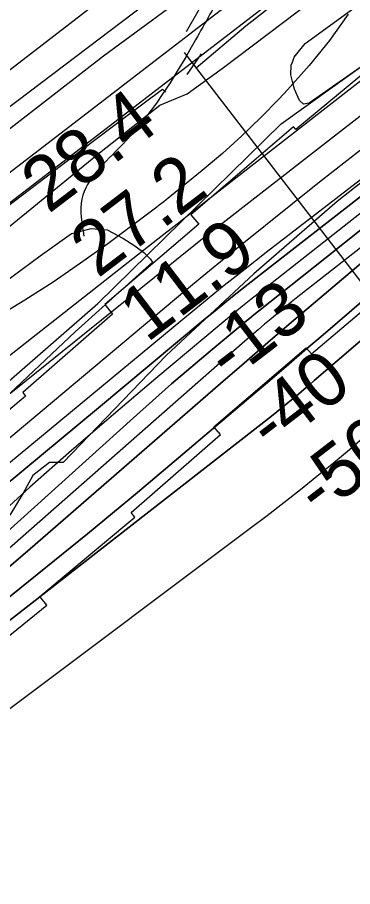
# Model space of a CAD drawing. Extents: x 3477039 to 3515015, y 546746 to 572297.
# Drawn here: x 3483912 to 3484325, y 559585 to 560657 of the extents above; entities that cross this region are included whole.
import ezdxf

# ---------------------------------------------------------------- set-up
doc = ezdxf.new("R2010")
doc.units = 0
for name, color, linetype in [('V-FLOD-BASE', 7, 'Continuous'), ('V-LEVE-TOET', 7, 'Continuous'), ('V-RIVR-EDGE', 7, 'Continuous'), ('V-RIVR-RANG', 7, 'Continuous'), ('V-ROAD-CNTR', 7, 'Continuous'), ('V-RRAP-FSHR', 7, 'Continuous'), ('V-RRAP-RVMT', 7, 'Continuous'), ('V-SITE-VEGE', 7, 'Continuous'), ('V-SURV-LINE', 7, 'Continuous'), ('V-TOPO-DPTH', 7, 'Continuous'), ('V-TOPO-MAJR', 7, 'Continuous'), ('V-TOPO-MINR', 7, 'Continuous'), ('V-TOPO-SHOR', 7, 'Continuous'), ('V-TOPO-WATR', 7, 'Continuous')]:
    doc.layers.add(name, color=color, linetype=linetype)

msp = doc.modelspace()

# ---------------------------------------------------------------- linework, layer by layer
at = {"layer": 'V-FLOD-BASE'}
for points in [[(3484132.1, 560594.4), (3484193.4, 560646.2), (3484285.1, 560718), (3484373.8, 560785.7), (3484477.9, 560867.4), (3484564.3, 560932.6)], [(3482382.9, 559248.9), (3482364.8, 559272), (3482401.5, 559301.2), (3482530.3, 559398.1), (3482669.5, 559501.2), (3482766.4, 559574.2), (3482900, 559673.3), (3483028.3, 559767.9), (3483135.8, 559846), (3483258.8, 559933.5), (3483358, 560002.3), (3483466.8, 560085.2), (3483528.9, 560136.6), (3483563.8, 560167.6), (3483599.3, 560196.2), (3483672.6, 560249.2), (3483768.9, 560321.6), (3483869.4, 560401), (3483974.7, 560480.9), (3484043.8, 560532.9), (3484090.5, 560567.9), (3484094.7, 560564.3)]]:
    msp.add_lwpolyline(points, dxfattribs=at)
at = {"layer": 'V-LEVE-TOET'}
for points in [[(3484546.9, 561015), (3484410.9, 560904), (3484276.1, 560799), (3484222.1, 560759.6), (3484143.1, 560701), (3484017.8, 560608.8), (3483855.8, 560483.3), (3483732.8, 560381.7), (3483580.9, 560267.9), (3483437.9, 560159.3), (3483302.5, 560057.2), (3483187.3, 559976.8), (3483022.3, 559850.1), (3482873.4, 559739.2), (3482703.1, 559613.2), (3482541.8, 559491.8), (3482433.6, 559410.7), (3482383.4, 559374.9), (3482356.2, 559355.3), (3482282.9, 559299.3), (3482194.2, 559234), (3482159.4, 559205)], [(3483226.6, 559872.4), (3483279.2, 559910.3), (3483320, 559941.2), (3483416.3, 560017.1), (3483486.7, 560072), (3483579, 560153.8), (3483683, 560231.4), (3483801.2, 560318.3), (3483902.9, 560399.5), (3484012.9, 560489.4), (3484087.4, 560548.4), (3484097.2, 560552.4), (3484121, 560562.3), (3484166, 560594.9), (3484275.3, 560677.2)]]:
    msp.add_lwpolyline(points, dxfattribs=at)
at = {"layer": 'V-RIVR-EDGE'}
msp.add_lwpolyline([(3484399.2, 560503), (3484305.9, 560429.7), (3484203.3, 560340.5), (3484095.2, 560239.6), (3483968.1, 560107.6), (3483951.5, 560107.6), (3483930.7, 560091.8), (3483919, 560069.7), (3483902.4, 560042.8)], dxfattribs=at)
at = {"layer": 'V-RIVR-RANG'}
msp.add_line((3484117.5, 560613.1), (3484483.4, 560137.6), dxfattribs=at)
at = {"layer": 'V-ROAD-CNTR'}
for points in [[(3487076.1, 563044), (3486779.2, 562810.3), (3486559.3, 562642), (3486392.2, 562506.5), (3486233.3, 562382.9), (3486038.4, 562229.6), (3485911.7, 562136), (3485621, 561911.1), (3485424, 561754.5), (3485308.3, 561665.3), (3485038, 561461.4), (3484792.2, 561271.1), (3484535.2, 561068.6), (3484336.9, 560919.3), (3484215.5, 560832), (3484122, 560761.2), (3483893.9, 560584.8), (3483720.5, 560448), (3483575.7, 560335.3), (3483437.8, 560223.9), (3483274.8, 560095.3), (3483188.4, 560027.1), (3483006, 559900.9)], [(3484219.5, 560834.8), (3484122, 560761.2), (3483893.9, 560584.8), (3483720.5, 560448), (3483575.7, 560335.3), (3483437.8, 560223.9), (3483274.8, 560095.3), (3483188.4, 560027.1), (3483006, 559900.9)], [(3484204, 560804.4), (3484205.9, 560791.9), (3484206, 560790.3), (3484205.7, 560787.7), (3484204.8, 560785.4), (3484195.1, 560767.8), (3484184.5, 560749.6), (3484168.1, 560722.7), (3484151.6, 560695.4), (3484134.1, 560663.6), (3484119.8, 560638.8)], [(3484138.2, 560611.7), (3484120.7, 560586.2)]]:
    msp.add_lwpolyline(points, dxfattribs=at)
msp.add_spline([(3484207, 560825.5), (3484220.2, 560798), (3484218.5, 560779.2), (3484197.4, 560742), (3484164.6, 560687.9), (3484129.2, 560625), (3484040.4, 560499), (3483991.3, 560432.4), (3483993.7, 560386.9)], degree=3, dxfattribs=at)
at = {"layer": 'V-RRAP-FSHR'}
msp.add_lwpolyline([(3481235.5, 558175), (3481260.4, 558193.2), (3481664.8, 558468.2), (3481750.1, 558561.3), (3481840.8, 558681.4), (3481906.4, 558774.6), (3482006.9, 558887.3), (3482130.2, 558983.5), (3482201, 559023.4), (3482476.9, 559192.1), (3482732, 559365.8), (3482809.3, 559398.5), (3482880.6, 559442.7), (3483189.7, 559671.5), (3483435.4, 559838.7), (3483794.7, 560115.6), (3484011.1, 560303.9), (3484237, 560525.2), (3484364.2, 560616.5), (3484735.6, 560876.4)], dxfattribs=at)
at = {"layer": 'V-RRAP-RVMT'}
for points in [[(3484495.5, 560702.4), (3484380.4, 560606.2), (3484372.1, 560615.4), (3484255.2, 560518.1), (3484252.3, 560521.4), (3484125.6, 560412.9), (3484135.6, 560401.4), (3484019.4, 560302.5), (3484029.1, 560290.7), (3483918.3, 560194), (3483921.9, 560189.6), (3483811.6, 560096.8), (3483801.4, 560108.9), (3483687.5, 560012.6), (3483683.1, 560017.4), (3483574.6, 559926.1), (3483571.2, 559930), (3483452, 559827.6)], [(3483452, 559827.6), (3483614.7, 559633.7), (3483734.2, 559733.9), (3483733, 559735.4), (3483842.4, 559825.2), (3483832.3, 559838.2), (3483948, 559931.9), (3483939.2, 559942.5), (3484056.5, 560040.4), (3484051.9, 560046), (3484162.2, 560142.1), (3484154, 560151.8), (3484267.9, 560248.9), (3484274.2, 560241.7), (3484399.6, 560347.6), (3484397.4, 560350.1), (3484617.7, 560539.2)]]:
    msp.add_lwpolyline(points, dxfattribs=at)
at = {"layer": 'V-SITE-VEGE'}
for points in [[(3484465.8, 560687.9), (3484350.6, 560606.2), (3484271.4, 560550.8), (3484264.3, 560549.7), (3484259.6, 560553.9), (3484253.3, 560568), (3484250.8, 560577.5), (3484248.7, 560585.7), (3484249.3, 560597.5), (3484250.8, 560601.5), (3484252.9, 560607.4), (3484266.5, 560624.4), (3484396, 560718.9)], [(3483806.4, 560264), (3483940, 560362.6), (3483978.4, 560390), (3484002.6, 560396.3), (3484022.6, 560394.4), (3484041.9, 560384.3), (3484056.6, 560374.8), (3484067.7, 560366.5), (3484075.3, 560358.8), (3484078.2, 560354.6), (3483982.9, 560268.7), (3483887.7, 560179.3)]]:
    msp.add_lwpolyline(points, dxfattribs=at)
at = {"layer": 'V-SURV-LINE'}
for points in [[(3483525, 560175.6), (3487277.1, 563062.8)], [(3487295.4, 563039), (3483543.3, 560151.8)]]:
    msp.add_lwpolyline(points, dxfattribs=at)
at = {"layer": 'V-TOPO-DPTH'}
for points in [[(3484837.9, 560882.1), (3484351.8, 560505.8), (3484318, 560479.6), (3484284.4, 560453.2), (3484250.9, 560426.7), (3484217.5, 560400), (3484184.2, 560373.2), (3484151.1, 560346.2), (3484118.2, 560319), (3483523.4, 559820.4), (3483490.6, 559793.6), (3483438.3, 559751.1), (3483431.5, 559745.7), (3483424.7, 559740.3), (3483417.7, 559735.2), (3483410.7, 559730.1), (3483341.6, 559681.1), (3483299.9, 559651.7), (3483258.1, 559622.4), (3483216.1, 559593.4)], [(3483157, 559406.5), (3483242.5, 559466.9), (3483327.8, 559527.6), (3483470.5, 559629.8), (3483484.2, 559639.7), (3483497.8, 559649.8), (3483511.3, 559660.1), (3483524.6, 559670.6), (3483643, 559764.7), (3483715, 559822.8), (3483786.6, 559881.5), (3483857.4, 559941.1), (3483927.6, 560001.4), (3484162, 560205.1), (3484191.2, 560230.3), (3484220.4, 560255.5), (3484249.7, 560280.6), (3484279.1, 560305.6), (3484332.8, 560351.2), (3484389.4, 560398.7), (3484446.3, 560445.7), (3484503.7, 560492.1), (3484561.5, 560538), (3484939.8, 560835.2)], [(3483157, 559406.5), (3483242.5, 559466.9), (3483327.8, 559527.6), (3483470.5, 559629.8), (3483484.2, 559639.7), (3483497.8, 559649.8), (3483511.3, 559660.1), (3483524.6, 559670.6), (3483643, 559764.7), (3483715, 559822.8), (3483786.6, 559881.5), (3483857.4, 559941.1), (3483927.6, 560001.4), (3484162, 560205.1), (3484191.2, 560230.3), (3484220.4, 560255.5), (3484249.7, 560280.6), (3484279.1, 560305.6), (3484332.8, 560351.2), (3484389.4, 560398.7), (3484446.3, 560445.7), (3484503.7, 560492.1), (3484561.5, 560538), (3484939.8, 560835.2)], [(3484938.5, 560763.4), (3484474.6, 560376.2), (3484439.4, 560346.7), (3484404.3, 560317), (3484369.3, 560287.3), (3484334.4, 560257.4), (3484277.8, 560208.7), (3484271.3, 560203.1), (3484264.7, 560197.6), (3484258.2, 560192), (3484251.6, 560186.5), (3484245, 560181.1), (3484238.3, 560175.6), (3484231.6, 560170.3), (3484224.9, 560165), (3483582.3, 559663.7), (3483552.8, 559641), (3483523.2, 559618.4), (3483493.3, 559596.2), (3483463.3, 559574.2), (3482731.9, 559044.5)], [(3482731.9, 559044.5), (3483463.3, 559574.2), (3483493.3, 559596.2), (3483523.2, 559618.4), (3483552.8, 559641), (3483582.3, 559663.7), (3484224.9, 560165), (3484231.6, 560170.3), (3484238.3, 560175.6), (3484245, 560181.1), (3484251.6, 560186.5), (3484258.2, 560192), (3484264.7, 560197.6), (3484271.3, 560203.1), (3484277.8, 560208.7), (3484334.4, 560257.4), (3484369.3, 560287.3), (3484404.3, 560317), (3484439.4, 560346.7), (3484474.6, 560376.2), (3484938.5, 560763.4)], [(3484787.4, 560692.9), (3484742.6, 560655.4), (3484698, 560617.5), (3484288.7, 560265.3), (3484265.8, 560245.6), (3484243, 560226), (3484220, 560206.5), (3484197.1, 560186.9), (3484121.1, 560122.3), (3484059.9, 560070.8), (3483998.3, 560019.8), (3483936.1, 559969.4), (3483873.5, 559919.6), (3483553.4, 559667.2), (3483532, 559650.6), (3483510.5, 559634.2), (3483488.7, 559618), (3483466.9, 559602.1), (3483079.9, 559323.5)], [(3483079.9, 559323.5), (3483466.9, 559602.1), (3483488.7, 559618), (3483510.5, 559634.2), (3483532, 559650.6), (3483553.4, 559667.2), (3483873.5, 559919.6), (3483936.1, 559969.4), (3483998.3, 560019.8), (3484059.9, 560070.8), (3484121.1, 560122.3), (3484197.1, 560186.9), (3484220, 560206.5), (3484243, 560226), (3484265.8, 560245.6), (3484288.7, 560265.3), (3484698, 560617.5), (3484742.6, 560655.4), (3484787.4, 560692.9)], [(3484669.5, 560695.8), (3484618.4, 560656.2), (3484215.3, 560342.5), (3484196.1, 560327.5), (3484177, 560312.3), (3484158.1, 560296.9), (3484139.3, 560281.4), (3484011.9, 560175.3), (3483681.7, 559901.3), (3483493.3, 559745.6), (3483471.2, 559727.8), (3483448.9, 559710.4), (3483426.1, 559693.5), (3483403.1, 559676.9), (3483095.1, 559460.8)], [(3483095.1, 559460.8), (3483403.1, 559676.9), (3483426.1, 559693.5), (3483448.9, 559710.4), (3483471.2, 559727.8), (3483493.3, 559745.6), (3483681.7, 559901.3), (3484011.9, 560175.3), (3484139.3, 560281.4), (3484158.1, 560296.9), (3484177, 560312.3), (3484196.1, 560327.5), (3484215.3, 560342.5), (3484618.4, 560656.2), (3484669.5, 560695.8)], [(3484337.3, 560396.1), (3484290.7, 560359.2), (3484209, 560294.4), (3484203.3, 560289.8), (3484197.7, 560285.3), (3484192.1, 560280.7), (3484186.5, 560276), (3484149.5, 560245.1), (3484125.6, 560224.9), (3484101.9, 560204.5), (3484078.4, 560183.8), (3484055, 560162.9), (3484000.4, 560113.5), (3483949.7, 560067.9), (3483899, 560022.4)], [(3483899, 560022.4), (3483949.7, 560067.9), (3484000.4, 560113.5), (3484055, 560162.9), (3484078.4, 560183.8), (3484101.9, 560204.5), (3484125.6, 560224.9), (3484149.5, 560245.1), (3484186.5, 560276), (3484192.1, 560280.7), (3484197.7, 560285.3), (3484203.3, 560289.8), (3484209, 560294.4), (3484290.7, 560359.2), (3484337.3, 560396.1)]]:
    msp.add_lwpolyline(points, dxfattribs=at)
at = {"layer": 'V-TOPO-MAJR'}
for points in [[(3484933.1, 560672.9), (3484913.1, 560655.1), (3484360.5, 560157.9), (3484341, 560140.6), (3484321.3, 560123.5), (3484301.3, 560106.8), (3484281.1, 560090.3), (3484260.7, 560074.1), (3484240.2, 560058), (3484219.5, 560042.1), (3484198.7, 560026.3), (3483610.6, 559585.3), (3483591.8, 559571.1), (3483573.1, 559556.7), (3483554.6, 559542), (3483536.1, 559527.3), (3483120.6, 559190.6)], [(3484319.7, 560660.6), (3484296.5, 560628.2), (3484271.3, 560597.2), (3484244.9, 560567.3), (3484234.5, 560556.2), (3484211.9, 560533), (3484188.6, 560510.4), (3484164.5, 560488.8), (3484139.7, 560467.9), (3484095, 560431.5), (3484092.2, 560429.2), (3484089.3, 560427), (3484086.4, 560424.8), (3484083.5, 560422.6), (3484023.2, 560377.4), (3483989.7, 560353.3), (3483955.8, 560329.9), (3483921, 560307.7), (3483885.7, 560286.3)]]:
    msp.add_lwpolyline(points, dxfattribs=at)
at = {"layer": 'V-TOPO-MINR'}
for points in [[(3484770, 560917.6), (3484156.7, 560439.2), (3484132.7, 560420.4), (3484108.7, 560401.6), (3484084.7, 560382.9), (3483499.6, 559923.3), (3483454.1, 559887.7), (3483378.2, 559828.3), (3483370.6, 559822.4), (3483363, 559816.6), (3483355.3, 559810.9), (3483347.6, 559805.3), (3483259.8, 559741.6), (3483208.1, 559704.3)], [(3484837.9, 560882.1), (3484351.8, 560505.8), (3484318, 560479.6), (3484284.4, 560453.2), (3484250.9, 560426.7), (3484217.5, 560400), (3484184.2, 560373.2), (3484151.1, 560346.2), (3484118.2, 560319), (3483523.4, 559820.4), (3483490.6, 559793.6), (3483438.3, 559751.1), (3483431.5, 559745.7), (3483424.7, 559740.3), (3483417.7, 559735.2), (3483410.7, 559730.1), (3483341.6, 559681.1), (3483299.9, 559651.7), (3483258.1, 559622.4), (3483216.1, 559593.4)], [(3484835.7, 560842.5), (3484218.6, 560366.5), (3484192.6, 560346.2), (3484166.7, 560325.8), (3484141.1, 560305.1), (3484115.6, 560284.2), (3483773.7, 560001.3), (3483706.5, 559945.9), (3483639.2, 559890.5), (3483571.9, 559835.3), (3483465.8, 559748.3), (3483451.4, 559736.7), (3483436.8, 559725.3), (3483421.9, 559714.3), (3483406.9, 559703.5), (3483264.8, 559603.2), (3483178.5, 559542.6)], [(3484939.8, 560835.2), (3484561.5, 560538), (3484503.7, 560492.1), (3484446.3, 560445.7), (3484389.4, 560398.7), (3484332.8, 560351.2), (3484279.1, 560305.6), (3484249.7, 560280.6), (3484220.4, 560255.5), (3484191.2, 560230.3), (3484162, 560205.1), (3483927.6, 560001.4), (3483857.4, 559941.1), (3483786.6, 559881.5), (3483715, 559822.8), (3483643, 559764.7), (3483524.6, 559670.6), (3483511.3, 559660.1), (3483497.8, 559649.8), (3483484.2, 559639.7), (3483470.5, 559629.8), (3483327.8, 559527.6), (3483242.5, 559466.9), (3483157, 559406.5)], [(3484927.8, 560836.5), (3484257.6, 560311.8), (3484249.2, 560305.2), (3484241, 560298.6), (3484232.7, 560291.8), (3484224.6, 560285), (3484216.5, 560278.2), (3484208.4, 560271.3), (3484200.4, 560264.3), (3484192.3, 560257.3), (3483785.4, 559899.6), (3483737.4, 559858), (3483689.1, 559816.9), (3483640.2, 559776.5), (3483590.9, 559736.6), (3483510.2, 559672.2), (3483500.9, 559664.9), (3483491.5, 559657.6), (3483482, 559650.6), (3483472.4, 559643.6), (3483374.2, 559573.5), (3483315.3, 559531.8), (3483256.2, 559490.3), (3483196.8, 559449.3)], [(3484938.5, 560763.4), (3484474.6, 560376.2), (3484439.4, 560346.7), (3484404.3, 560317), (3484369.3, 560287.3), (3484334.4, 560257.4), (3484277.8, 560208.7), (3484271.3, 560203.1), (3484264.7, 560197.6), (3484258.2, 560192), (3484251.6, 560186.5), (3484245, 560181.1), (3484238.3, 560175.6), (3484231.6, 560170.3), (3484224.9, 560165), (3483582.3, 559663.7), (3483552.8, 559641), (3483523.2, 559618.4), (3483493.3, 559596.2), (3483463.3, 559574.2), (3482731.9, 559044.5)], [(3484787.4, 560692.9), (3484742.6, 560655.4), (3484698, 560617.5), (3484288.7, 560265.3), (3484265.8, 560245.6), (3484243, 560226), (3484220, 560206.5), (3484197.1, 560186.9), (3484121.1, 560122.3), (3484059.9, 560070.8), (3483998.3, 560019.8), (3483936.1, 559969.4), (3483873.5, 559919.6), (3483553.4, 559667.2), (3483532, 559650.6), (3483510.5, 559634.2), (3483488.7, 559618), (3483466.9, 559602.1), (3483079.9, 559323.5)], [(3484507.6, 560669.5), (3484431.9, 560610.6), (3484356.2, 560551.7), (3484280.5, 560492.8), (3484150.7, 560391.9), (3484139.9, 560383.5), (3484129.1, 560375), (3483365.7, 559760.3), (3483338.7, 559740.6), (3482809.6, 559362.6)], [(3484378.4, 560449.2), (3484212.1, 560318.5), (3484199.7, 560308.7), (3484187.4, 560298.8), (3484175.1, 560288.8), (3484162.9, 560278.7), (3484082.3, 560211.2), (3484030.2, 560167), (3483978.4, 560122.4), (3483927.2, 560077.1), (3483876.4, 560031.3)], [(3484337.3, 560396.1), (3484290.7, 560359.2), (3484209, 560294.4), (3484203.3, 560289.8), (3484197.7, 560285.3), (3484192.1, 560280.7), (3484186.5, 560276), (3484149.5, 560245.1), (3484125.6, 560224.9), (3484101.9, 560204.5), (3484078.4, 560183.8), (3484055, 560162.9), (3484000.4, 560113.5), (3483949.7, 560067.9), (3483899, 560022.4)]]:
    msp.add_lwpolyline(points, dxfattribs=at)
at = {"layer": 'V-TOPO-SHOR'}
msp.add_lwpolyline([(3484198.7, 560771.2), (3483839.7, 560499), (3483291.2, 560064.9)], dxfattribs=at)
at = {"layer": 'V-TOPO-WATR'}
msp.add_lwpolyline([(3484669.5, 560695.8), (3484618.4, 560656.2), (3484215.3, 560342.5), (3484196.1, 560327.5), (3484177, 560312.3), (3484158.1, 560296.9), (3484139.3, 560281.4), (3484011.9, 560175.3), (3483681.7, 559901.3), (3483493.3, 559745.6), (3483471.2, 559727.8), (3483448.9, 559710.4), (3483426.1, 559693.5), (3483403.1, 559676.9), (3483095.1, 559460.8)], dxfattribs=at)

# ---------------------------------------------------------------- texts
at = {"layer": 'V-RIVR-RANG'}
for s, rotation, p in [('28.4', 37.2583, (3483950, 560413.6)), ('27.2', 37.2583, (3484010.8, 560334.2)), ('11.9', 37.2583, (3484071.3, 560254.6)), ('-13', 37.5405, (3484173.1, 560206)), ('-40', 37.5405, (3484224.8, 560119.6)), ('-50', 37.5405, (3484283.9, 560038.9))]:
    msp.add_text(s, height=67, rotation=rotation, dxfattribs=at).set_placement(p)

doc.saveas('drawing.dxf')
